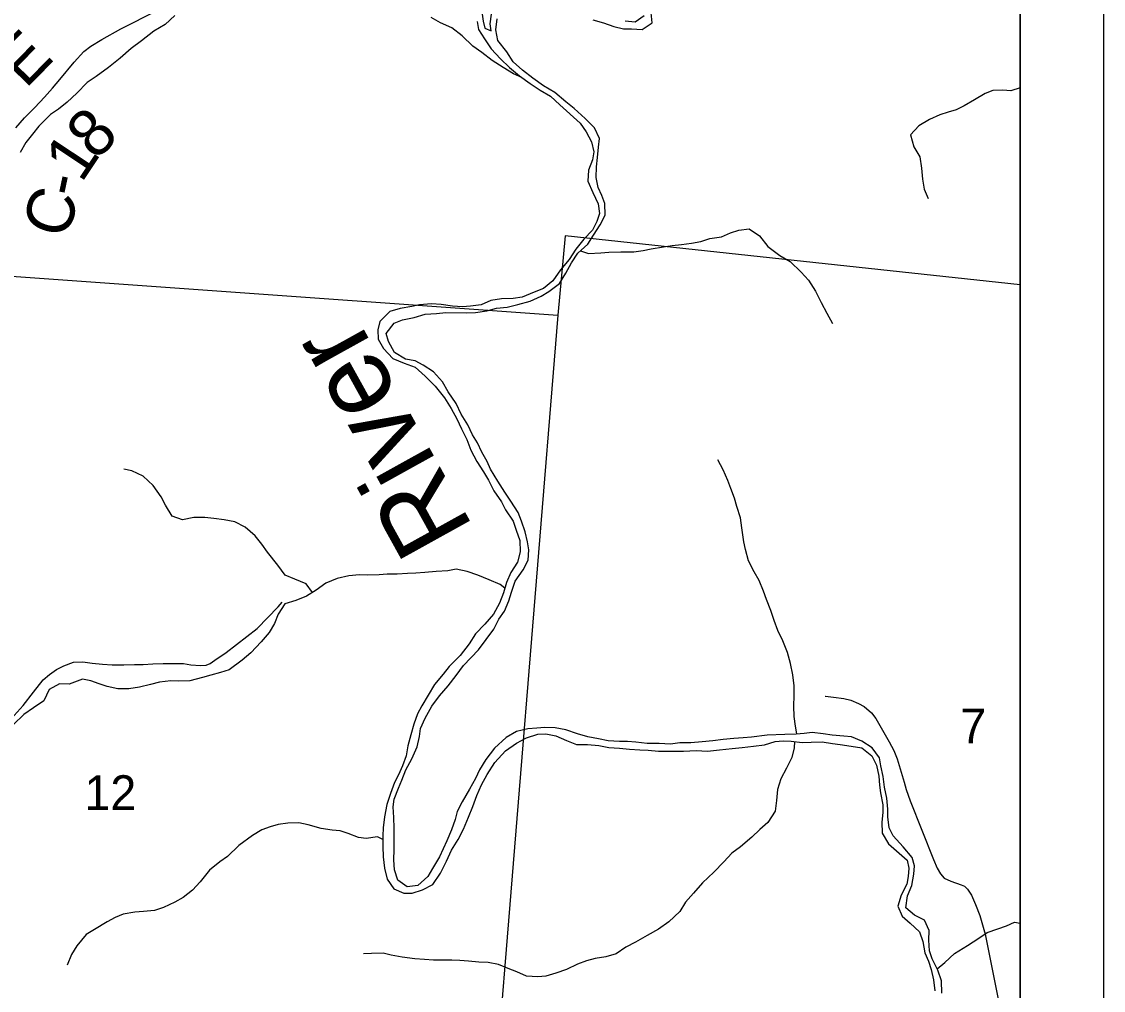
# Model space of a CAD drawing. Extents: x 0 to 40.8, y 0 to 22.
# Drawn here: x 7.699 to 9, y 15.058 to 16.222 of the extents above; entities that cross this region are included whole.
import ezdxf

# ---------------------------------------------------------------- set-up
doc = ezdxf.new("R2010")
doc.units = 0
for name, color, linetype in [('Default', 7, 'Continuous'), ('GM_X_County_Road', 7, 'Continuous'), ('GM_X_County_Road_Text', 7, 'Continuous'), ('GM_X_Major_River', 7, 'Continuous'), ('GM_X_Major_River_Text', 7, 'Continuous'), ('GM_X_Minor_River', 7, 'Continuous'), ('GM_X_Section', 7, 'Continuous'), ('GM_X_Section_Text', 7, 'Continuous'), ('GM_X_Township_Road', 7, 'Continuous'), ('SH_Cut_Line', 7, 'Continuous'), ('SH_Data', 7, 'Continuous')]:
    doc.layers.add(name, color=color, linetype=linetype)

msp = doc.modelspace()

# ---------------------------------------------------------------- linework, layer by layer
at = {"layer": 'Default'}
msp.add_lwpolyline([(2.1, 16.4387), (2.1, 14.1), (8.9, 14.1), (8.9, 16.9831), (7.7161, 17.0658), (7.7144, 17.066), (7.54, 17.0745), (7.4495, 17.0841), (6.9172, 17.1197), (6.1785, 17.166), (5.6278, 17.197), (5.3407, 17.2146), (4.8294, 17.2493), (4.5348, 17.2687), (3.4481, 17.3334), (3.1244, 17.3534), (2.8484, 17.3691), (2.8463, 17.3693), (2.4594, 17.3966), (2.4379, 17.0913), (2.3911, 16.4258)], close=True, dxfattribs=at)
at = {"layer": 'GM_X_County_Road'}
msp.add_lwpolyline([(7.6925, 16.0945), (7.7029, 16.1067), (7.7154, 16.1189), (7.7271, 16.1314), (7.7367, 16.1421), (7.7456, 16.1525), (7.7627, 16.1733), (7.7744, 16.1861), (7.7825, 16.1927), (7.7957, 16.2008), (7.8189, 16.2135), (7.8624, 16.2354)], dxfattribs=at)
msp.add_lwpolyline([(8.9, 14.8634), (8.9, 15.9059), (8.353, 15.9646), (8.344, 15.8695), (8.2661, 14.9102)], close=True, dxfattribs=at)
at = {"layer": 'GM_X_Major_River'}
for points in [[(8.2416, 16.2677), (8.2393, 16.2653), (8.2392, 16.2574), (8.2457, 16.2486), (8.2506, 16.2399), (8.2532, 16.2312), (8.2543, 16.2228), (8.2562, 16.2145), (8.2638, 16.211), (8.2627, 16.2194), (8.2642, 16.2312)], [(8.3862, 16.2245), (8.3991, 16.2207), (8.4116, 16.2165), (8.4229, 16.2134), (8.4328, 16.2134), (8.4456, 16.2126), (8.4574, 16.2206), (8.4563, 16.2327)], [(8.247, 16.2223), (8.2489, 16.2128), (8.2561, 16.2014), (8.264, 16.1893), (8.275, 16.1775), (8.286, 16.1672), (8.2981, 16.157), (8.311, 16.1479), (8.3227, 16.1399), (8.3352, 16.1327), (8.3466, 16.1221), (8.3708, 16.1001), (8.378, 16.0899), (8.3845, 16.0777), (8.3875, 16.0656), (8.386, 16.0561), (8.3811, 16.0436), (8.3803, 16.0303), (8.3864, 16.017), (8.3928, 16.003), (8.3943, 15.9916), (8.3909, 15.9821), (8.386, 15.9715), (8.3754, 15.9609), (8.3659, 15.9487), (8.3576, 15.9362), (8.3473, 15.9237), (8.3382, 15.9108), (8.3269, 15.9013), (8.3155, 15.8972), (8.3011, 15.8911), (8.2905, 15.8896), (8.2765, 15.8892), (8.2636, 15.8869), (8.2518, 15.882), (8.2393, 15.8801), (8.2295, 15.8793), (8.2174, 15.8801), (8.2037, 15.8824), (8.1924, 15.8831), (8.178, 15.882), (8.1685, 15.8797), (8.1545, 15.8774), (8.142, 15.8736), (8.1302, 15.8619), (8.1276, 15.8516), (8.1283, 15.8406), (8.1344, 15.8293), (8.1458, 15.8175), (8.1594, 15.8118), (8.1727, 15.8069), (8.1848, 15.7959), (8.1965, 15.7841), (8.2079, 15.7701)], [(8.2527, 15.7046), (8.2474, 15.716), (8.2417, 15.7255), (8.2361, 15.7376), (8.2281, 15.7505), (8.2217, 15.7631), (8.2123, 15.7771), (8.2055, 15.7893), (8.1945, 15.8014), (8.1824, 15.8094), (8.1726, 15.8144), (8.1608, 15.8167), (8.1479, 15.8246), (8.1404, 15.8379), (8.1378, 15.8474), (8.1473, 15.8596), (8.1575, 15.8637), (8.1715, 15.8667), (8.1848, 15.8705), (8.1984, 15.8712), (8.2094, 15.8724), (8.2348, 15.8723), (8.245, 15.8727), (8.2587, 15.8745), (8.2704, 15.8776), (8.2833, 15.8791), (8.2962, 15.8821), (8.311, 15.8862), (8.3239, 15.8923), (8.3333, 15.8979), (8.3462, 15.9074), (8.3538, 15.9199), (8.3607, 15.9321), (8.3683, 15.9438), (8.38, 15.9548), (8.3872, 15.9654), (8.3952, 15.9779), (8.4009, 15.9896), (8.4006, 16.0037), (8.3972, 16.0132), (8.3927, 16.0227), (8.3904, 16.0348), (8.3908, 16.0477), (8.392, 16.0587), (8.3931, 16.0712), (8.3943, 16.0818), (8.3882, 16.0944), (8.3769, 16.1058), (8.3636, 16.1179), (8.3538, 16.1259), (8.3406, 16.1369), (8.3269, 16.1449), (8.3141, 16.1544), (8.3016, 16.1639), (8.2906, 16.1738), (8.2827, 16.186), (8.2721, 16.1997), (8.2695, 16.2122), (8.271, 16.2255)], [(8.4478, 16.2291), (8.4372, 16.2215), (8.425, 16.2226)], [(8.2079, 15.7701), (8.2158, 15.7572), (8.2227, 15.7447), (8.2283, 15.7329), (8.2348, 15.72), (8.2397, 15.7071), (8.2469, 15.6934), (8.2548, 15.6809), (8.2609, 15.6711), (8.267, 15.6582), (8.2764, 15.6449), (8.2814, 15.6354), (8.2905, 15.6217), (8.2942, 15.6111), (8.2984, 15.5986), (8.2988, 15.5849), (8.2957, 15.5724), (8.2878, 15.5599), (8.2825, 15.5481), (8.2787, 15.5356), (8.2738, 15.5231), (8.2666, 15.5102), (8.2563, 15.4981), (8.245, 15.4863), (8.2374, 15.4742), (8.2268, 15.4605), (8.2135, 15.4472), (8.2063, 15.4377), (8.1957, 15.4256), (8.1805, 15.3998), (8.1756, 15.3903), (8.1711, 15.3778), (8.1673, 15.3649), (8.1639, 15.3516), (8.1616, 15.3399), (8.1574, 15.3277), (8.1525, 15.3171), (8.1479, 15.3076), (8.143, 15.2943), (8.1385, 15.2811), (8.1358, 15.2666), (8.1343, 15.2534), (8.1339, 15.2435), (8.1339, 15.2306), (8.1343, 15.2185), (8.1358, 15.2048), (8.1388, 15.1915), (8.1468, 15.1798), (8.1589, 15.1745), (8.1688, 15.1745), (8.1813, 15.1786), (8.1938, 15.1851), (8.2029, 15.1987), (8.2104, 15.2131), (8.2161, 15.2264), (8.2245, 15.2393), (8.2309, 15.2518), (8.2366, 15.2659), (8.2419, 15.2788), (8.2468, 15.2921), (8.2525, 15.305), (8.259, 15.3175), (8.2684, 15.3319), (8.2813, 15.3456), (8.2946, 15.355), (8.3063, 15.3615), (8.32, 15.3657), (8.3298, 15.366), (8.3416, 15.3638), (8.3544, 15.3581), (8.3666, 15.3535), (8.3798, 15.3535), (8.3935, 15.352), (8.4056, 15.3497), (8.4181, 15.349), (8.4302, 15.3478), (8.4427, 15.3471), (8.4526, 15.3467), (8.4651, 15.3455), (8.4749, 15.3452), (8.4848, 15.3452), (8.4954, 15.3455), (8.5105, 15.3463), (8.5242, 15.3455), (8.5386, 15.3471), (8.5537, 15.3486), (8.5658, 15.3497), (8.5795, 15.3512), (8.5927, 15.3531), (8.6056, 15.3569), (8.6151, 15.3577), (8.6246, 15.3573), (8.6378, 15.3558), (8.6488, 15.3561), (8.6621, 15.3565), (8.6742, 15.3546), (8.6837, 15.3535), (8.6969, 15.3512), (8.7098, 15.3493), (8.7216, 15.3398), (8.7272, 15.3284)], [(8.741, 15.2663), (8.741, 15.2758), (8.7396, 15.2887), (8.7369, 15.302), (8.7351, 15.3149), (8.7324, 15.3278), (8.7309, 15.3373), (8.7219, 15.3495), (8.7097, 15.3575), (8.6972, 15.3624), (8.6878, 15.3632), (8.6741, 15.3647), (8.6632, 15.3663), (8.6499, 15.3678), (8.6404, 15.3667), (8.6306, 15.3659), (8.6169, 15.3652), (8.5957, 15.3645), (8.5768, 15.3622), (8.5669, 15.3615), (8.5556, 15.3604), (8.5431, 15.3592), (8.5305, 15.3578), (8.5177, 15.3566), (8.504, 15.3555), (8.4908, 15.3555), (8.4794, 15.3537), (8.4658, 15.3544), (8.4514, 15.3545), (8.4381, 15.356), (8.4279, 15.3568), (8.4184, 15.3568), (8.4048, 15.3576), (8.393, 15.3603), (8.3801, 15.3625), (8.3677, 15.366), (8.3536, 15.3709), (8.3411, 15.3732), (8.3283, 15.3736), (8.3188, 15.3729), (8.3082, 15.3721), (8.2945, 15.3691), (8.282, 15.3619), (8.268, 15.3491), (8.2574, 15.3354), (8.2498, 15.3229), (8.2452, 15.3123), (8.238, 15.2998), (8.2292, 15.2843), (8.2231, 15.2729), (8.2205, 15.2634), (8.2163, 15.2509), (8.2106, 15.2376), (8.2064, 15.2278), (8.2018, 15.2183), (8.1935, 15.2043), (8.1878, 15.1948), (8.176, 15.1838), (8.1628, 15.1823), (8.1518, 15.1903), (8.1476, 15.2028), (8.1469, 15.2149), (8.1473, 15.2271), (8.1473, 15.2529), (8.147, 15.2658), (8.1462, 15.2783), (8.1474, 15.2878), (8.1527, 15.3007), (8.1565, 15.3105), (8.1615, 15.3231), (8.1687, 15.3363), (8.1752, 15.3504), (8.1778, 15.3629), (8.179, 15.3727), (8.1847, 15.3849), (8.1927, 15.3993), (8.2018, 15.4118), (8.2124, 15.4239), (8.2219, 15.4364), (8.2306, 15.4482), (8.2489, 15.4671), (8.258, 15.4796), (8.2671, 15.4921), (8.2732, 15.5039), (8.28, 15.5137), (8.2853, 15.5262), (8.2884, 15.5365), (8.293, 15.5497), (8.3024, 15.5634), (8.3085, 15.5748), (8.3093, 15.5873), (8.3078, 15.5968), (8.3048, 15.6089), (8.3003, 15.6218), (8.2965, 15.6324), (8.2878, 15.6457), (8.2803, 15.6567), (8.2719, 15.67), (8.2633, 15.6841), (8.2591, 15.6936), (8.2527, 15.7046)], [(8.7272, 15.3284), (8.7299, 15.3155), (8.731, 15.3045), (8.7322, 15.2951), (8.7348, 15.281), (8.7348, 15.2715), (8.7337, 15.2602), (8.734, 15.2469), (8.7416, 15.234), (8.7511, 15.2256), (8.764, 15.2142), (8.7662, 15.2048), (8.7655, 15.1949), (8.7636, 15.1854), (8.7571, 15.1721), (8.753, 15.1592), (8.7583, 15.1471), (8.7677, 15.1387), (8.7791, 15.1281), (8.7829, 15.1164), (8.7852, 15.1031), (8.7897, 15.0928), (8.7931, 15.083), (8.7958, 15.0705), (8.7973, 15.0572)], [(8.8058, 15.0545), (8.8055, 15.0693), (8.801, 15.0822), (8.7942, 15.0959), (8.7908, 15.1054), (8.79, 15.1183), (8.7904, 15.1297), (8.7848, 15.1422), (8.773, 15.1483), (8.7624, 15.157), (8.7647, 15.1715), (8.7697, 15.184), (8.772, 15.1976), (8.7728, 15.2075), (8.7701, 15.2174), (8.7595, 15.2303), (8.7471, 15.2436), (8.7425, 15.2531), (8.741, 15.2663)]]:
    msp.add_lwpolyline(points, dxfattribs=at)
at = {"layer": 'GM_X_Minor_River'}
for points in [[(7.8837, 16.2295), (7.8719, 16.2189), (7.8586, 16.2109), (7.8435, 16.1991), (7.831, 16.1897), (7.8181, 16.1783), (7.8041, 16.1669), (7.7889, 16.1563), (7.7783, 16.1491), (7.7658, 16.1362), (7.7544, 16.1252), (7.7438, 16.1168), (7.734, 16.1104), (7.7203, 16.0964), (7.7124, 16.0869), (7.7044, 16.077), (7.6976, 16.0649)], [(8.3007, 16.1552), (8.2909, 16.1593), (8.2784, 16.1669), (8.2652, 16.1756), (8.2527, 16.1851), (8.2421, 16.1927), (8.2292, 16.2052), (8.2167, 16.2147), (8.203, 16.2207), (8.1917, 16.2272)], [(8.9, 16.1427), (8.8888, 16.1391), (8.8793, 16.1399), (8.8672, 16.1395), (8.8577, 16.1357), (8.8452, 16.1281), (8.8327, 16.121), (8.8232, 16.116), (8.8133, 16.1134), (8.8035, 16.11), (8.791, 16.1047), (8.7781, 16.0968), (8.7682, 16.0862), (8.772, 16.0717), (8.7795, 16.0596), (8.7814, 16.0459), (8.7825, 16.033), (8.7844, 16.0209), (8.7893, 16.0095)], [(8.3713, 15.9466), (8.3811, 15.9434), (8.3959, 15.9445), (8.4054, 15.9453), (8.4198, 15.9456), (8.4357, 15.9456), (8.4467, 15.9471), (8.4562, 15.949), (8.4713, 15.9516), (8.4816, 15.9531), (8.4929, 15.9542), (8.5047, 15.9561), (8.516, 15.958), (8.527, 15.9614), (8.5407, 15.9636), (8.5517, 15.9682), (8.5619, 15.9716), (8.574, 15.9731), (8.5865, 15.9647), (8.5967, 15.9518), (8.6111, 15.9411), (8.6236, 15.9339), (8.6368, 15.921), (8.6455, 15.9115), (8.6538, 15.8982), (8.6606, 15.8845), (8.6674, 15.8716), (8.6742, 15.8595)], [(8.049, 15.5359), (8.0414, 15.5463), (8.0281, 15.5521), (8.0164, 15.557), (8.0073, 15.5688), (7.9952, 15.5844), (7.9884, 15.5942), (7.9801, 15.6041), (7.9684, 15.6144), (7.9559, 15.6208), (7.943, 15.6235), (7.9305, 15.6251), (7.9199, 15.6262), (7.9067, 15.6262), (7.893, 15.6232), (7.8805, 15.6278), (7.8726, 15.6411), (7.8673, 15.651), (7.8575, 15.6646), (7.8454, 15.6757), (7.8321, 15.6821), (7.8223, 15.6844)], [(8.6314, 15.366), (8.6298, 15.3754), (8.6283, 15.3872), (8.628, 15.3993), (8.6284, 15.4122), (8.6284, 15.424), (8.6265, 15.4369), (8.6239, 15.4509), (8.6201, 15.4638), (8.6145, 15.4779), (8.6088, 15.4904), (8.6043, 15.5026), (8.6001, 15.5143), (8.5949, 15.5276), (8.5915, 15.5375), (8.5862, 15.5504), (8.5801, 15.5607), (8.5734, 15.5743), (8.5696, 15.5876), (8.5677, 15.5971), (8.5655, 15.6138), (8.5636, 15.6259), (8.5594, 15.6396), (8.5564, 15.6495), (8.5523, 15.6612), (8.5485, 15.6707), (8.5429, 15.6836), (8.5364, 15.6954)], [(8.2804, 15.5413), (8.2748, 15.5456), (8.2615, 15.5513), (8.2479, 15.557), (8.235, 15.5612), (8.2218, 15.5639), (8.2119, 15.562), (8.1979, 15.5613), (8.1842, 15.5602), (8.1733, 15.5594), (8.1634, 15.5587), (8.1509, 15.5579), (8.1388, 15.5579), (8.1293, 15.5572), (8.1157, 15.5568), (8.1058, 15.5572), (8.0929, 15.5561), (8.0789, 15.5527), (8.0653, 15.5471), (8.0535, 15.5387), (8.0421, 15.5315), (8.0292, 15.5266), (8.016, 15.5225), (8.008, 15.51), (8.0034, 15.4986), (7.997, 15.488), (7.9875, 15.4766), (7.9749, 15.4634), (7.9647, 15.4547), (7.9488, 15.4433), (7.9385, 15.4399), (7.9268, 15.4365), (7.9169, 15.4339), (7.9018, 15.4297), (7.8881, 15.4294), (7.8787, 15.4297), (7.8654, 15.4283), (7.8544, 15.4256), (7.8411, 15.4222), (7.8283, 15.4203), (7.815, 15.4204), (7.8025, 15.423), (7.7927, 15.4261), (7.7828, 15.4299), (7.7726, 15.4318), (7.7567, 15.4258), (7.7449, 15.4262), (7.7324, 15.4194), (7.7263, 15.4057), (7.7138, 15.3974), (7.702, 15.3894), (7.6895, 15.3773)], [(8.6286, 15.3568), (8.6284, 15.3493), (8.6253, 15.3376), (8.6189, 15.325), (8.6124, 15.3121), (8.6083, 15.2992), (8.6071, 15.286), (8.6056, 15.2731), (8.5965, 15.2598), (8.587, 15.2514), (8.5772, 15.242), (8.5639, 15.2302), (8.5533, 15.2226), (8.5438, 15.2124), (8.5317, 15.1998), (8.5181, 15.187), (8.5071, 15.1748), (8.4976, 15.1638), (8.4908, 15.1528), (8.4775, 15.1403), (8.465, 15.1316), (8.4514, 15.1236), (8.4374, 15.1156), (8.426, 15.1099), (8.4143, 15.1016), (8.4018, 15.0982), (8.3889, 15.0963), (8.3786, 15.0932), (8.3677, 15.0895), (8.3544, 15.083), (8.3419, 15.0785), (8.3298, 15.075), (8.3199, 15.0743), (8.3063, 15.075), (8.2949, 15.08), (8.2843, 15.0841), (8.2726, 15.0891), (8.2604, 15.0914), (8.2491, 15.0917), (8.2369, 15.0929), (8.2263, 15.0936), (8.2165, 15.094), (8.1945, 15.094), (8.1839, 15.0948), (8.1722, 15.0959), (8.157, 15.0978), (8.1437, 15.1001), (8.1343, 15.1024), (8.1203, 15.102), (8.1104, 15.1016)], [(8.1339, 15.239), (8.1275, 15.2424), (8.1138, 15.2405), (8.1044, 15.2416), (8.0922, 15.2462), (8.0824, 15.2496), (8.0729, 15.2503), (8.0597, 15.2526), (8.0438, 15.2568), (8.0328, 15.2591), (8.0195, 15.2587), (8.0078, 15.2572), (7.9983, 15.2545), (7.9881, 15.2507), (7.9771, 15.2439), (7.9608, 15.2321), (7.9471, 15.2189), (7.9377, 15.2124), (7.9255, 15.2022), (7.9142, 15.1881), (7.9051, 15.1783), (7.8937, 15.1695), (7.8835, 15.1638), (7.8702, 15.1574), (7.8592, 15.154), (7.846, 15.1525), (7.8354, 15.1517), (7.8217, 15.1494), (7.8119, 15.1456), (7.8024, 15.1403), (7.7872, 15.1312), (7.777, 15.1248), (7.766, 15.1115), (7.7596, 15.1009), (7.7543, 15.088)], [(8.8002, 15.0838), (8.8093, 15.0913), (8.8211, 15.1023), (8.8366, 15.1118), (8.8503, 15.1205), (8.8601, 15.1273), (8.873, 15.1318), (8.8836, 15.1356), (8.8931, 15.1398), (8.9, 15.1385)]]:
    msp.add_lwpolyline(points, dxfattribs=at)
at = {"layer": 'GM_X_Section'}
msp.add_lwpolyline([(8.344, 15.8695), (8.2661, 14.9102), (8.2617, 14.8595), (7.7715, 14.8766), (7.2868, 14.9136), (7.3612, 15.9396)], close=True, dxfattribs=at)
at = {"layer": 'GM_X_Township_Road'}
for points in [[(7.6832, 15.3801), (7.7012, 15.4002), (7.7136, 15.4162), (7.7254, 15.431), (7.7328, 15.4376), (7.7412, 15.4437), (7.7501, 15.4481), (7.7618, 15.4524), (7.7732, 15.4529), (7.7844, 15.4511), (7.7966, 15.4498), (7.8085, 15.4491), (7.8225, 15.4491), (7.8353, 15.4496), (7.8454, 15.4496), (7.8571, 15.4503), (7.8696, 15.4506), (7.8838, 15.4508), (7.894, 15.4506), (7.9029, 15.4493), (7.9146, 15.4483), (7.9215, 15.4488), (7.926, 15.4508), (7.9319, 15.4549), (7.9452, 15.4638), (7.9828, 15.4928), (8.0077, 15.519), (8.0128, 15.5245)], [(8.6656, 15.4115), (8.6659, 15.4115), (8.6755, 15.4104), (8.6878, 15.4086), (8.6964, 15.4066), (8.7056, 15.4028), (8.7124, 15.399), (8.7213, 15.3913), (8.7264, 15.3845), (8.7424, 15.3567), (8.748, 15.3461), (8.7521, 15.3361), (8.7605, 15.3079), (8.763, 15.2993), (8.7679, 15.2858), (8.7958, 15.2153), (8.8002, 15.2047), (8.804, 15.1978), (8.8087, 15.1929), (8.8167, 15.1891), (8.8292, 15.1846), (8.8332, 15.183), (8.8368, 15.1795), (8.8414, 15.1724), (8.8464, 15.1611), (8.8513, 15.1477), (8.8579, 15.1253), (8.8754, 15.0371)]]:
    msp.add_lwpolyline(points, dxfattribs=at)
at = {"layer": 'SH_Cut_Line'}
msp.add_lwpolyline([(2.1, 17.4153), (2.1, 14.1), (8.9, 14.1), (8.9, 16.9831), (7.7161, 17.0658), (7.7144, 17.066), (7.54, 17.0745), (7.4495, 17.0841), (6.9172, 17.1197), (6.1785, 17.166), (5.6278, 17.197), (5.3407, 17.2146), (4.8294, 17.2493), (4.5348, 17.2687), (3.4481, 17.3334), (3.1244, 17.3534), (2.8484, 17.3691), (2.8463, 17.3693), (2.4594, 17.3966)], close=True, dxfattribs=at)
at = {"layer": 'SH_Data'}
for p, q in [((9, 21), (9, 14)), ((8.9, 20.9), (8.9, 14.1))]:
    msp.add_line(p, q, dxfattribs=at)

# ---------------------------------------------------------------- texts
at = {"layer": 'GM_X_County_Road_Text'}
for s, rotation, p in [('E', 45.6061, (7.7043, 16.1407)), ('8', 45.747, (7.7889, 16.0541)), ('1', 56.3749, (7.7713, 16.0272)), ('-', 78.1049, (7.7687, 16.0095)), ('C', 72.3377, (7.7529, 15.959))]:
    msp.add_text(s, height=0.0568, rotation=rotation, dxfattribs=at).set_placement(p)
at = {"layer": 'GM_X_Major_River_Text'}
msp.add_text('River', height=0.09468, rotation=119.0032, dxfattribs=at).set_placement((8.2435, 15.6132))
at = {"layer": 'GM_X_Section_Text'}
for s, height, p in [('7', 0.0419, (8.828, 15.3547)), ('12', 0.04186, (7.775, 15.2745))]:
    msp.add_text(s, height=height, rotation=0, dxfattribs=at).set_placement(p)

doc.saveas('drawing.dxf')
